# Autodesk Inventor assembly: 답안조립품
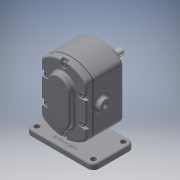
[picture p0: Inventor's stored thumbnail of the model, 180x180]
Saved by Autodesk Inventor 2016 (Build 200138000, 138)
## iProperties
Created: 2019-03
Part Number: 답안조립품
Material: 일반
Document SubType Name: Assembly
Designer: USER
Author: USER
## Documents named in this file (11)
- C:\Users\USER\Desktop\490307V1014\답안조립품.iam
- C:\Users\USER\Desktop\490307V1014\본체.ipt
- C:\Users\USER\Desktop\490307V1014\개스킷.ipt
- C:\Users\USER\Desktop\490307V1014\메인축.ipt
- C:\Users\USER\Desktop\490307V1014\베어링부시.ipt
- C:\Users\USER\Desktop\490307V1014\볼트 M5.ipt
- C:\Users\USER\Desktop\490307V1014\서브축.ipt
- C:\Users\USER\Desktop\490307V1014\스퍼기어.ipt
- C:\Users\USER\Desktop\490307V1014\오일 실 16 28 7.ipt
- C:\Users\USER\Desktop\490307V1014\커버.ipt
- C:\Users\USER\Desktop\490307V1014\키 6 x 6 x 18.ipt
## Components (1 placed, 1 different names)
1. 개스킷:1
